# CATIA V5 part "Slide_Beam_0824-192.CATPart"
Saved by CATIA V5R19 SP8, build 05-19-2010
Part number: Slide Beam 0824-192
Definition: Slide Beam 0824-192
Nomenclature: 60046
Material "Aluminium": density 2710 kg/m3, Young's modulus 7e+10 Pa, Poisson ratio 0.346, thermal expansion 2.36e-05 1/K
Bounding box of the stored display mesh (mm): x -96 to 96, y -12 to 12, z -4 to 4
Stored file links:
  D:\Documents\1_Travail\1 - ac-limoges.fr\ac-limoges.fr\Emmanuel Maynard - STI2D_Turgot\1 - IT-I2D\Activités_IT_Première\IT_3_Abris_bus\Maquettes numériques\Abribus_eleve\Slide_Beam_0824-192.CATPart
  D:\Documents\1_Travail\1 - ITEC_Turgot\6 -  Ressources ITEC\Ressources Techniques\0-Maquettes numériques_Composants\Makeblock\Catalogue_Makeblock_catia.xlsx
  D:\Documents\1_Travail\2- 2I2D\6 -  Ressources ITEC\Ressources Techniques\0-Maquettes numériques_Composants\Catalogue_Makeblock\Catalog_Makeblock\01_Profilés\Table_Beam0824.xls
  C:\Program Files\Dassault Systemes\B19\win_b64\startup\materials\French\Catalog.CATMaterial
  D:\Documents\1_Travail\2- 2I2D\6 -  Ressources ITEC\Ressources Techniques\0-Maquettes numériques_Composants\Catalogue_Makeblock\Catalog_Makeblock\01_Profilés\Table_Beam0824.txt
  D:\Documents\1_Travail\2- 2I2D\6 -  Ressources ITEC\Ressources Techniques\0-Maquettes numériques_Composants\Catalogue_Makeblock\Catalog_Makeblock\01_Profilés\Table_Slide_Beam0824.txt
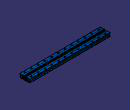
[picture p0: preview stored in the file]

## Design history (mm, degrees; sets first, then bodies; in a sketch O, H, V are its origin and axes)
Parameters
  Nb_Trous = 12
  Longueur = 192 mm
  Nb_Repet = 3
  Repet_Trou = false
  `Désignation` = "Slide Beam 0824-192"
  `Référence` = "60046"
AxisSystem1: origin (0, 0, 0), X (1, 0, 0), Y (0, 1, 0), Z (0, 0, 1)
Body1 (main body), material "Aluminium"
  Sketch1 on YZ plane of AxisSystem1, origin (0, 0, 0), H (0, 1, 0), V (0, 0, 1)
    line L1 (12, 4) -> (12, 2.9)
    line L2 (12, -4) -> (-12, -4)
    line L3 (-12, -4) -> (-12, -2.9)
    line L4 (-12, 4) -> (-1.6212, 4)
    point P1 (12, 4)
    point P2 (12, -4)
    point P5 (0, 1.1525)
    line L5 (1.6212, 3.65) -> (1.6212, 3.4386)
    line L6 (1.6212, -2.6) -> (-1.6212, -2.6)
    line L7 (-1.6212, -2.6) -> (-1.6212, -2.2192)
    line L8 (1.9496, 4) -> (12, 4)
    point P9 (-2.0758, 3.6427)
    line L9 (-2, 3.5989) -> (-1.6212, 3.3802)
    axis line L10 (-2.0758, 5.0021) -> (-2.0758, -2.577)
    reference intersected line E1 through (0, 0) direction (0, 1) from ZX plane of AxisSystem1
    arc A1 centre (-1.9705, 3.65) radius 0.059 from (-2, 3.7011) to (-2, 3.5989) ccw
    point P12 (-2, 3.7011)
    point P14 (-1.9705, 3.65)
    reference intersected line E2 through (0, 0) direction (0, 1) from ZX plane of AxisSystem1
    line L11 (-2, 3.7011) -> (-1.6212, 3.9198)
    point P16 (-1.6212, 3.9198)
    point P18 (-2, 3.0012)
    line L12 (-2, 3.0012) -> (-1.6212, 3.2199)
    point P20 (-1.9705, 2.9501)
    arc A2 centre (-1.9705, 2.9501) radius 0.059 from (-2, 3.0012) to (-2, 2.899) ccw
    line L13 (-2, 2.899) -> (-1.6212, 2.6803)
    point P23 (-2, 2.3013)
    line L14 (-2, 2.3013) -> (-1.6212, 2.52)
    point P25 (-1.9705, 2.2502)
    arc A3 centre (-1.9705, 2.2502) radius 0.059 from (-2, 2.3013) to (-2, 2.1991) ccw
    line L15 (-2, 2.1991) -> (-1.6212, 1.9803)
    point P28 (-2, 1.6013)
    line L16 (-2, 1.6013) -> (-1.6212, 1.8201)
    point P30 (-1.9705, 1.5502)
    arc A4 centre (-1.9705, 1.5502) radius 0.059 from (-2, 1.6013) to (-2, 1.4991) ccw
    line L17 (-2, 1.4991) -> (-1.6212, 1.2804)
    point P33 (-2, 0.9014)
    line L18 (-2, 0.9014) -> (-1.6212, 1.1201)
    point P35 (-1.9705, 0.8503)
    arc A5 centre (-1.9705, 0.8503) radius 0.059 from (-2, 0.9014) to (-2, 0.7992) ccw
    line L19 (-2, 0.7992) -> (-1.6212, 0.5805)
    point P38 (-2, 0.2015)
    line L20 (-2, 0.2015) -> (-1.6212, 0.4202)
    point P40 (-1.9705, 0.1504)
    arc A6 centre (-1.9705, 0.1504) radius 0.059 from (-2, 0.2015) to (-2, 0.0993) ccw
    line L21 (-2, 0.0993) -> (-1.6212, -0.1194)
    point P43 (-2, -0.4984)
    line L22 (-2, -0.4984) -> (-1.6212, -0.2797)
    point P45 (-1.9705, -0.5495)
    arc A7 centre (-1.9705, -0.5495) radius 0.059 from (-2, -0.4984) to (-2, -0.6006) ccw
    line L23 (-2, -0.6006) -> (-1.6212, -0.8193)
    point P48 (-2, -1.1983)
    line L24 (-2, -1.1983) -> (-1.6212, -0.9796)
    point P50 (-1.9705, -1.2494)
    arc A8 centre (-1.9705, -1.2494) radius 0.059 from (-2, -1.1983) to (-2, -1.3005) ccw
    line L25 (-2, -1.3005) -> (-1.6212, -1.5193)
    point P53 (-2, -1.8983)
    line L26 (-2, -1.8983) -> (-1.6212, -1.6795)
    point P55 (-1.9705, -1.9494)
    arc A9 centre (-1.9705, -1.9494) radius 0.059 from (-2, -1.8983) to (-2, -2.0005) ccw
    line L27 (-2, -2.0005) -> (-1.6212, -2.2192)
    point P57 (-2, -2.5982)
    point P58 (-2, -3.2981)
    line L28 (-1.6212, 3.9198) -> (-1.6212, 4)
    line L29 (-1.6212, 3.2199) -> (-1.6212, 3.3802)
    line L30 (-1.6212, 2.52) -> (-1.6212, 2.6803)
    line L31 (-1.6212, 1.8201) -> (-1.6212, 1.9803)
    line L32 (-1.6212, 1.1201) -> (-1.6212, 1.2804)
    line L33 (-1.6212, 0.4202) -> (-1.6212, 0.5805)
    line L34 (-1.6212, -0.2797) -> (-1.6212, -0.1194)
    line L35 (-1.6212, -0.9796) -> (-1.6212, -0.8193)
    line L36 (-1.6212, -1.6795) -> (-1.6212, -1.5193)
    line L37 (2, 3.9709) -> (1.9496, 4)
    arc A10 centre (1.9705, 3.9198) radius 0.059 from (2, 3.9709) to (2, 3.8687) cw
    point P64 (1.6212, 3.65)
    line L38 (2, 3.8687) -> (1.6212, 3.65)
    line L39 (2, 3.2199) -> (1.6212, 3.4386)
    arc A11 centre (1.9705, 3.1688) radius 0.059 from (2, 3.2199) to (2, 3.1177) cw
    line L40 (2, 3.1177) -> (1.6212, 2.899)
    line L41 (2, 2.4689) -> (1.6212, 2.6876)
    arc A12 centre (1.9705, 2.4178) radius 0.059 from (2, 2.4689) to (2, 2.3667) cw
    line L42 (2, 2.3667) -> (1.6212, 2.148)
    line L43 (2, 1.7179) -> (1.6212, 1.9366)
    arc A13 centre (1.9705, 1.6668) radius 0.059 from (2, 1.7179) to (2, 1.6157) cw
    line L44 (2, 1.6157) -> (1.6212, 1.397)
    line L45 (2, 0.9669) -> (1.6212, 1.1856)
    arc A14 centre (1.9705, 0.9158) radius 0.059 from (2, 0.9669) to (2, 0.8647) cw
    line L46 (2, 0.8647) -> (1.6212, 0.6459)
    line L47 (2, 0.2158) -> (1.6212, 0.4346)
    arc A15 centre (1.9705, 0.1647) radius 0.059 from (2, 0.2158) to (2, 0.1136) cw
    line L48 (2, 0.1136) -> (1.6212, -0.1051)
    line L49 (2, -0.5352) -> (1.6212, -0.3165)
    arc A16 centre (1.9705, -0.5863) radius 0.059 from (2, -0.5352) to (2, -0.6374) cw
    line L50 (2, -0.6374) -> (1.6212, -0.8561)
    line L51 (2, -1.2862) -> (1.6212, -1.0675)
    arc A17 centre (1.9705, -1.3373) radius 0.059 from (2, -1.2862) to (2, -1.3884) cw
    line L52 (2, -1.3884) -> (1.6212, -1.6071)
    line L53 (2, -2.0372) -> (1.6212, -1.8185)
    arc A18 centre (1.9705, -2.0883) radius 0.059 from (2, -2.0372) to (2, -2.1394) cw
    line L54 (2, -2.1394) -> (1.6212, -2.3581)
    line L55 (1.6212, -2.3581) -> (1.6212, -2.6)
    line L56 (1.6212, -1.6071) -> (1.6212, -1.8185)
    line L57 (1.6212, -0.8561) -> (1.6212, -1.0675)
    line L58 (1.6212, -0.1051) -> (1.6212, -0.3165)
    line L59 (1.6212, 0.6459) -> (1.6212, 0.4346)
    line L60 (1.6212, 1.397) -> (1.6212, 1.1856)
    line L61 (1.6212, 2.148) -> (1.6212, 1.9366)
    line L62 (1.6212, 2.899) -> (1.6212, 2.6876)
    point P106 (12, 2.9)
    line L63 (12, 2.9) -> (10.6, 1.5)
    point P107 (10.6, 1.5)
    line L64 (10.6, 1.5) -> (10.6, -1.5)
    point P108 (10.6, -1.5)
    line L65 (10.6, -1.5) -> (12, -2.9)
    point P109 (12, -2.9)
    line L66 (12, -2.9) -> (12, -4)
    arc A19 centre (8, 0) radius 1.65 from (6.5, -0.6874) to (6.5, 0.6874) ccw
    point P110 (8, 0)
    point P111 (7.521, -1.579)
    reference intersected line E4 through (0, 0) direction (0, 1) from ZX plane of AxisSystem1
    point P112 (4.7206, 0)
    line L67 (6.5, 2.95) -> (6.5, 0.6874)
    line L68 (6.2, -3.25) -> (3.2412, -3.25)
    line L69 (2.9412, -2.95) -> (2.9412, 2.95)
    line L70 (3.2412, 3.25) -> (6.2, 3.25)
    point P113 (6.3398, -1.5387)
    point P114 (6.5, -0.9716)
    point P115 (6.5, 0.6874)
    point P116 (6.5, 0.6874)
    line L71 (6.5, -0.6874) -> (6.5, -2.95)
    arc A20 centre (3.2412, 2.95) radius 0.3 from (2.9412, 2.95) to (3.2412, 3.25) cw
    point P117 (2.9412, 2.95)
    point P118 (3.2412, 3.25)
    arc A21 centre (6.2, 2.95) radius 0.3 from (6.5, 2.95) to (6.2, 3.25) ccw
    point P120 (6.5, 2.95)
    point P121 (6.2, 3.25)
    arc A22 centre (6.2, -2.95) radius 0.3 from (6.2, -3.25) to (6.5, -2.95) ccw
    point P123 (6.2, -3.25)
    point P124 (6.5, -2.95)
    arc A23 centre (3.2412, -2.95) radius 0.3 from (3.2412, -3.25) to (2.9412, -2.95) cw
    point P126 (3.2412, -3.25)
    point P127 (2.9412, -2.95)
    reference projected line E5 through (0, 0) direction (0, 1) from edge [ZX plane of AxisSystem1 | YZ plane of AxisSystem1]
    point P131 (-12, 4)
    point P132 (-12, -4)
    point P133 (-12, 2.9)
    point P134 (-10.6, 1.5)
    point P135 (-10.6, -1.5)
    point P136 (-12, -2.9)
    point P138 (-7.521, -1.579)
    point P139 (-4.7206, 0)
    point P140 (-6.3398, -1.5387)
    point P141 (-6.5, 0.6874)
    point P142 (-6.5, 0.6874)
    point P143 (-2.9412, 2.95)
    point P144 (-3.2412, 3.25)
    point P146 (-6.5, 2.95)
    point P147 (-6.2, 3.25)
    point P149 (-6.2, -3.25)
    point P150 (-6.5, -2.95)
    point P152 (-3.2412, -3.25)
    point P153 (-2.9412, -2.95)
    line L72 (-12, 2.9) -> (-10.6, 1.5)
    line L73 (-10.6, 1.5) -> (-10.6, -1.5)
    line L74 (-10.6, -1.5) -> (-12, -2.9)
    arc A24 centre (-8, 0) radius 1.65 from (-6.5, -0.6874) to (-6.5, 0.6874) cw
    line L75 (-6.5, 2.95) -> (-6.5, 0.6874)
    line L76 (-6.2, -3.25) -> (-3.2412, -3.25)
    line L77 (-2.9412, -2.95) -> (-2.9412, 2.95)
    line L78 (-3.2412, 3.25) -> (-6.2, 3.25)
    line L79 (-6.5, -0.6874) -> (-6.5, -2.95)
    arc A25 centre (-3.2412, 2.95) radius 0.3 from (-2.9412, 2.95) to (-3.2412, 3.25) ccw
    arc A26 centre (-6.2, 2.95) radius 0.3 from (-6.5, 2.95) to (-6.2, 3.25) cw
    arc A27 centre (-6.2, -2.95) radius 0.3 from (-6.2, -3.25) to (-6.5, -2.95) cw
    arc A28 centre (-3.2412, -2.95) radius 0.3 from (-3.2412, -3.25) to (-2.9412, -2.95) ccw
    line L80 (-12, 2.9) -> (-12, 4)
    distance L3 L1 = 24
    distance L2 L4 = 8
    distance L7 L5 = 3.2423
    distance L4 L6 = 6.6
    distance L10 E1 = 2.0758
    distance P12 E2 = 2
    distance P14 L4 = 0.35
    angle L11 L9 = 60
    angle L11 L10 = 60
    angle L12 L13 = 60
    distance P18 E2 = 2 (reference)
    distance P20 L4 = 1.0499 (reference)
    angle L12 L10 = 60 (reference)
    angle L14 L15 = 60
    distance P25 L4 = 1.7498 (reference)
    distance P23 E2 = 2 (reference)
    angle L14 L10 = 60 (reference)
    angle L16 L17 = 60
    distance P28 E2 = 2 (reference)
    distance P30 L4 = 2.4498 (reference)
    angle L16 L10 = 60 (reference)
    angle L18 L19 = 60
    distance P33 E2 = 2 (reference)
    distance P35 L4 = 3.1497 (reference)
    angle L18 L10 = 60 (reference)
    angle L20 L21 = 60
    distance P40 L4 = 3.8496 (reference)
    distance P38 E2 = 2 (reference)
    angle L20 L10 = 60 (reference)
    angle L22 L23 = 60
    distance P43 E2 = 2 (reference)
    distance P45 L4 = 4.5495 (reference)
    angle L22 L10 = 60 (reference)
    angle L24 L25 = 60
    distance P48 E2 = 2 (reference)
    distance P50 L4 = 5.2494 (reference)
    angle L24 L10 = 60 (reference)
    angle L26 L27 = 60
    distance P55 L4 = 5.9494 (reference)
    distance P53 E2 = 2 (reference)
    angle L26 L10 = 60 (reference)
    distance P57 E2 = 2 (reference)
    distance P58 E2 = 2 (reference)
    distance L64 L1 = 1.4
    angle L65 L2 = 45
    distance P110 E4 = 8
    radius A19 = 1.65
    distance L8 L70 = 0.75
    distance L69 P64 = 1.32
    radius A20 = 0.3
    radius A21 = 0.3
    radius A22 = 0.3
    radius A23 = 0.3
    distance L67 P110 = 1.5
    length L64 = 3
    distance P108 P110 V = 1.5
    vertical: L1 V, L3 V, L5 V, L7 V, L10 V, L28 V, L29 V, L30 V, L31 V, L32 V, L33 V, L34 V, L35 V, L36 V, L55 V, L56 V, L57 V, L58 V, L59 V, L60 V, L61 V, L62 V, L64 V, L66 V, L67 V, L69 V, L71 V, L80 V
    horizontal: L2 H, L4 H, L6 H, L8 H, L68 H, L70 H
    equidistance: L1 L3 O, L2 L4 O, L5 L7 P5, L67 L69 P112, L68 L70 P112
    coincidence: P5 V, L4 L8, P9 L10, L9 P9, L7 P16, L7 L28, L7 L29, L7 L30, L7 L31, L7 L32, L7 L33, L7 L34, L7 L35, L7 L36, L5 L55, L5 L56, L5 L57, L5 L58, L5 L59, L5 L60, L5 L61, L5 L62, P109 L1, L1 L66, P110 H, A19 P111, P111 L63, P112 H, L67 P114, L67 L71, L3 L80, P116 P115, P114 L71
    tangency: A1 L9, L11 A1, A2 L13, L12 A2, A3 L15, L14 A3, A4 L17, L16 A4, L18 A5, A5 L19, A6 L21, L20 A6, A7 L23, L22 A7, L24 A8, A8 L25, A9 L27, L26 A9, A20 L69, A20 L70, A21 L67, A21 L70, A22 L68, A22 L71, A23 L68, A23 L69
    perpendicularity: L63 L65
    symmetry: P1 P131 E5, P2 P132 E5, P106 P133 E5, P107 P134 E5, P108 P135 E5, P109 P136 E5, P111 P138 E5, P112 P139 E5, P113 P140 E5, P115 P141 E5, P116 P142 E5, P117 P143 E5, P118 P144 E5, P120 P146 E5, P121 P147 E5, P123 P149 E5, P124 P150 E5, P126 P152 E5, P127 P153 E5, L63 L72 E5, L64 L73 E5, L65 L74 E5, A19 A24 E5, L67 L75 E5, L68 L76 E5, L69 L77 E5, L70 L78 E5, L71 L79 E5, A20 A25 E5, A21 A26 E5, A22 A27 E5, A23 A28 E5
  Pad1: profile Sketch1, direction (1, 0, 0), length 96 {= Longueur /2}, mirrored extent
  Fillet1: radius 0.2, on edge [face of Pad1 from Sketch1.L8 | face of Pad1 from Sketch1.L1]; edge [face of Pad1 from Sketch1.L1 | face of Pad1 from Sketch1.L63]; edge [face of Pad1 from Sketch1.L64 | face of Pad1 from Sketch1.L65]; edge [face of Pad1 from Sketch1.L63 | face of Pad1 from Sketch1.L64]; edge [face of Pad1 from Sketch1.L65 | face of Pad1 from Sketch1.L66]; edge [face of Pad1 from Sketch1.L66 | face of Pad1 from Sketch1.L2]; edge [face of Pad1 from Sketch1.L80 | face of Pad1 from Sketch1.L4]; edge [face of Pad1 from Sketch1.L72 | face of Pad1 from Sketch1.L80]; edge [face of Pad1 from Sketch1.L73 | face of Pad1 from Sketch1.L72]; edge [face of Pad1 from Sketch1.L74 | face of Pad1 from Sketch1.L73]; edge [face of Pad1 from Sketch1.L3 | face of Pad1 from Sketch1.L74]; edge [face of Pad1 from Sketch1.L2 | face of Pad1 from Sketch1.L3]
  Sketch2 on face of Pad1 from Sketch1.L8, origin (0, 0, 4), H (1, 0, 0), V (0, 1, 0)
    circle A1 centre (88, 8) radius 1.5641
    point P1 (88, 8)
    circle A2 centre (88, -8) radius 1.7249
    point P2 (88, -8)
    reference intersected line E1 through (96, 0) direction (0, 1) from end face of Pad1
    reference intersected line E2 through (96, 0) direction (0, 1) from end face of Pad1
    reference projected line E3 through (0, 8) direction (1, 0) from axis of face of Pad1 from Sketch1.A19
    reference projected line E4 through (0, -8) direction (1, 0) from axis of face of Pad1 from Sketch1.A24
    distance P1 E1 = 8
    distance P2 E2 = 8
    coincidence: P1 E3, P2 E4
  Pocket1: profile Sketch2, direction (0, 0, -1), through (limit type 3)
  RectPattern1: of Pocket1, direction 1 instances 12 {= Nb_Trous}, spacing 16, along edge [face of Pad1 from Sketch1.L37 | face of Pad1 from Sketch1.L8] reversed
  RectPattern2: of RectPattern1, direction 1 instances 3 {= Nb_Repet}, spacing 0 {= (Longueur/2) -(16mm*(Nb_Trous /2))}, along edge [face of Pad1 from Sketch1.L8 | face of Fillet1] reversed, deactivated
Relations
  RectPattern2.Activity = Repet_Trou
